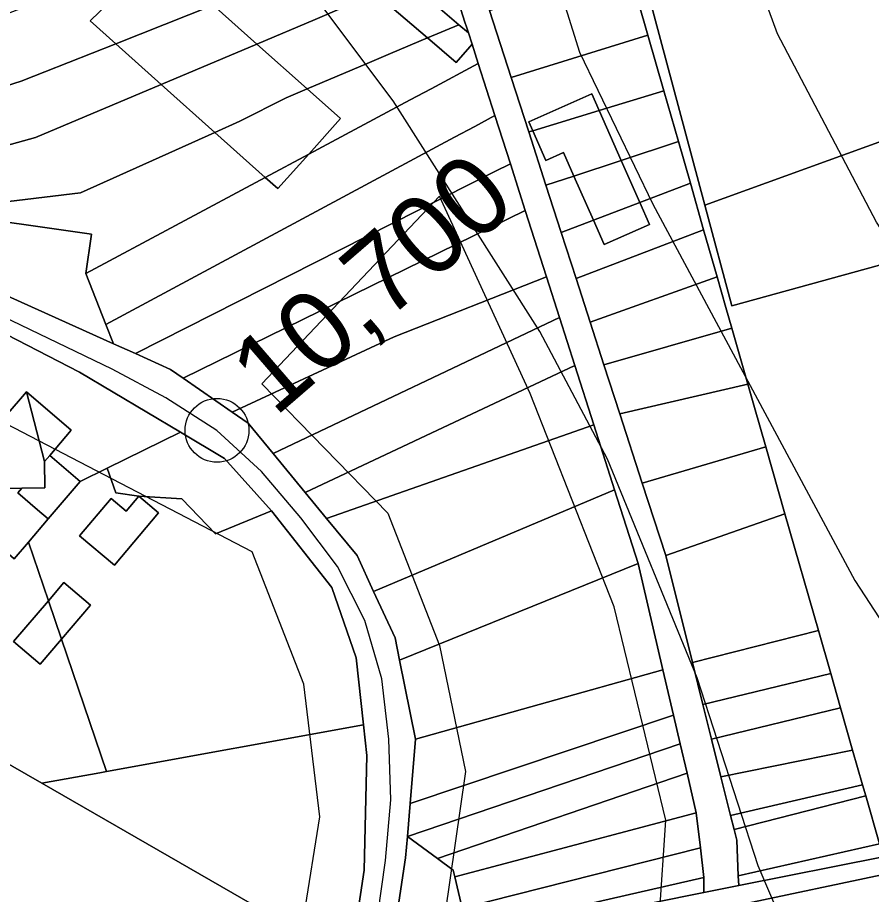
# Model space of a CAD drawing. Extents: x -510989 to -501240, y -1184665 to -1176089.
# Drawn here: x -509299.4 to -509158.8, y -1180046.7 to -1179902.3 of the extents above; entities that cross this region are included whole.
import ezdxf

# ---------------------------------------------------------------- set-up
doc = ezdxf.new("R2010")
doc.units = 0
for name, color, linetype in [('orna_puda', 7, 'Continuous'), ('ostatni_plocha_x_manipulacni_plocha', 7, 'Continuous'), ('STAV_systematicke_odvodneni', 7, 'Continuous'), ('trasovani_toku', 7, 'Continuous'), ('trvaly_travni_porost', 7, 'Continuous'), ('vodni_plocha_x_vodni_tok_v_koryte_umelem', 7, 'Continuous'), ('vrstevnice_01', 7, 'Continuous'), ('vrstevnice_02', 7, 'Continuous'), ('zastavena_plocha_a_nadvori', 7, 'Continuous')]:
    doc.layers.add(name, color=color, linetype=linetype)

msp = doc.modelspace()

# ---------------------------------------------------------------- linework, layer by layer
at = {"layer": 'orna_puda'}
msp.add_lwpolyline([(-509551.44, -1180058.44), (-509541.37, -1180032.19), (-509505.8, -1180014.94), (-509485.03, -1180004.33), (-509426.69, -1179970.89), (-509421.83, -1179967.93), (-509416.14, -1179964.47), (-509408.66, -1179958.69), (-509398.69, -1179948.99), (-509395.92, -1179946.29), (-509388.88, -1179961.65), (-509388.82, -1179965.62), (-509388.69, -1179974.07), (-509378.19, -1179980.22), (-509365.84, -1179987.46), (-509338.79, -1180003.3), (-509322.79, -1180012.68), (-509322.74, -1180012.71), (-509295.45, -1180028.39), (-509258.93, -1180049.38)], dxfattribs=at)
at = {"layer": 'ostatni_plocha_x_manipulacni_plocha'}
for points in [[(-509279.16, -1179893.19), (-509280.4, -1179894.4), (-509279.63, -1179895.2), (-509287.49, -1179902.86), (-509283.28, -1179906.61), (-509298.86, -1179912.78), (-509345.31, -1179927.56), (-509354.67, -1179922.9), (-509338.41, -1179915.88)], [(-509253.51, -1179894.83), (-509247.36, -1179892.39), (-509240.41, -1179898.36), (-509246.46, -1179900.92), (-509250.44, -1179902.6), (-509260.03, -1179906.66), (-509267.21, -1179900.25), (-509257.67, -1179896.48)], [(-509235.24, -1179896.18), (-509228.82, -1179893.47), (-509225.76, -1179903.05), (-509225.52, -1179903.8), (-509225.19, -1179904.81), (-509226.76, -1179903.47)], [(-509221.74, -1179901.11), (-509198.71, -1179894.43), (-509195.63, -1179905.19), (-509218.17, -1179912.14)], [(-509246.46, -1179900.92), (-509240.41, -1179898.36), (-509231.92, -1179905.65), (-509238.01, -1179908.23), (-509241.87, -1179909.86), (-509251.76, -1179914.04), (-509260.03, -1179906.66), (-509250.44, -1179902.6)], [(-509218.17, -1179912.14), (-509195.63, -1179905.19), (-509193, -1179914.38), (-509203.69, -1179917.62), (-509204.89, -1179914.88), (-509215.25, -1179919.45), (-509214.6, -1179920.92), (-509215.27, -1179921.12)], [(-509298.86, -1179912.78), (-509283.28, -1179906.61), (-509275.78, -1179913.31), (-509296.5, -1179922.05), (-509334.69, -1179932.64), (-509345.31, -1179927.56)], [(-509238.01, -1179908.23), (-509231.92, -1179905.65), (-509227.22, -1179909.7), (-509224.6, -1179906.65), (-509223.58, -1179909.86), (-509231.33, -1179914.01), (-509234.78, -1179915.86), (-509251.49, -1179924.79), (-509246.27, -1179918.94), (-509251.76, -1179914.04), (-509241.87, -1179909.86)], [(-509231.33, -1179914.01), (-509223.58, -1179909.86), (-509220.84, -1179918.43), (-509224.16, -1179920.21), (-509227.51, -1179922.01), (-509284.89, -1179952.84), (-509288.21, -1179944.42), (-509258.64, -1179928.61), (-509256.56, -1179930.46), (-509251.49, -1179924.79), (-509234.78, -1179915.86)], [(-509275.78, -1179913.31), (-509266.94, -1179921.2), (-509289.06, -1179931.17), (-509314.67, -1179934.24), (-509322.46, -1179933.61), (-509334.69, -1179932.64), (-509296.5, -1179922.05)], [(-509203.69, -1179917.62), (-509193, -1179914.38), (-509190.61, -1179922.72), (-509200.06, -1179925.84)], [(-509224.16, -1179920.21), (-509220.84, -1179918.43), (-509218.29, -1179926.38), (-509220.83, -1179927.67), (-509280, -1179957.64), (-509283.64, -1179956), (-509284.89, -1179952.84), (-509227.51, -1179922.01)], [(-509266.94, -1179921.2), (-509258.64, -1179928.61), (-509288.21, -1179944.42), (-509287.28, -1179937.97), (-509311.6, -1179934.48), (-509314.67, -1179934.24), (-509289.06, -1179931.17)], [(-509215.27, -1179921.12), (-509214.6, -1179920.92), (-509212.43, -1179925.82), (-509209.53, -1179924.54), (-509207.83, -1179928.4), (-509212.43, -1179929.91)], [(-509200.06, -1179925.84), (-509190.61, -1179922.72), (-509188.65, -1179929.58), (-509196.99, -1179932.77)], [(-509220.83, -1179927.67), (-509218.29, -1179926.38), (-509216.78, -1179931.09), (-509215.83, -1179934.07), (-509272.16, -1179961.67), (-509274.23, -1179960.24), (-509280, -1179957.64)], [(-509212.43, -1179929.91), (-509207.83, -1179928.4), (-509204.61, -1179935.68), (-509209.91, -1179937.7)], [(-509196.99, -1179932.77), (-509188.65, -1179929.58), (-509186.47, -1179937.23), (-509207.46, -1179945.27), (-509209.91, -1179937.7), (-509204.61, -1179935.68), (-509202.85, -1179939.66), (-509195.4, -1179936.37)], [(-509212.33, -1179945), (-509237.41, -1179954.86), (-509264.12, -1179967.25), (-509272.16, -1179961.67), (-509215.83, -1179934.07)], [(-509311.6, -1179934.48), (-509287.28, -1179937.97), (-509288.21, -1179944.42), (-509284.89, -1179952.84), (-509283.64, -1179956), (-509308.5, -1179944.81)], [(-509186.47, -1179937.23), (-509184.24, -1179945.01), (-509205.14, -1179952.44), (-509207.46, -1179945.27)], [(-509210.2, -1179951.69), (-509257.36, -1179974.08), (-509261.47, -1179969.08), (-509264.12, -1179967.25), (-509237.41, -1179954.86), (-509212.33, -1179945)], [(-509184.24, -1179945.01), (-509182.8, -1179950.04), (-509181.82, -1179953.46), (-509202.87, -1179959.47), (-509205.14, -1179952.44)], [(-509308.37, -1179951.14), (-509303.03, -1179953.6), (-509289.24, -1179960.67), (-509272.59, -1179970.58), (-509284.66, -1179976.49), (-509289.12, -1179978.67), (-509294.14, -1179974.39), (-509290.6, -1179970.25), (-509297.99, -1179963.94), (-509301.31, -1179967.84), (-509303.11, -1179962.06)], [(-509207.66, -1179959.6), (-509252.09, -1179980.48), (-509257.36, -1179974.08), (-509210.2, -1179951.69)], [(-509202.87, -1179959.47), (-509181.82, -1179953.46), (-509179.19, -1179962.66), (-509200.25, -1179967.55)], [(-509204.54, -1179969.37), (-509248.57, -1179984.76), (-509252.09, -1179980.48), (-509207.66, -1179959.6)], [(-509179.19, -1179962.66), (-509178.09, -1179966.51), (-509176.23, -1179972.99), (-509196.56, -1179978.97), (-509200.25, -1179967.55)], [(-509201.12, -1179980.06), (-509240.8, -1179996.81), (-509243.51, -1179990.9), (-509248.57, -1179984.76), (-509204.54, -1179969.37)], [(-509272.59, -1179970.58), (-509265.34, -1179974.89), (-509257.62, -1179983.54), (-509266.85, -1179987.32), (-509272.39, -1179981.57), (-509279.49, -1179981.11), (-509283.26, -1179980.55), (-509284.66, -1179976.49)], [(-509196.56, -1179978.97), (-509176.23, -1179972.99), (-509173.08, -1179984), (-509192.71, -1179990.88)], [(-509283.26, -1179980.55), (-509279.49, -1179981.11), (-509281.57, -1179983.59), (-509284.05, -1179981.5), (-509289.22, -1179987.65), (-509283.48, -1179992.48), (-509276.22, -1179983.86), (-509279.49, -1179981.11), (-509272.39, -1179981.57), (-509266.85, -1179987.32), (-509257.62, -1179983.54), (-509247.71, -1179996.14), (-509243.68, -1180007.74), (-509242.47, -1180018.79), (-509284.8, -1180026.46), (-509292.2, -1180004.67), (-509287.42, -1179999.06), (-509291.8, -1179995.32), (-509294.36, -1179998.32), (-509297.64, -1179988.66), (-509294.4, -1179984.86), (-509289.12, -1179978.67), (-509284.66, -1179976.49)], [(-509310.38, -1179979.84), (-509306.18, -1179979.82), (-509309.3, -1179983.48), (-509301.77, -1179989.91), (-509300, -1179991.42), (-509297.64, -1179988.66), (-509294.36, -1179998.32), (-509300.1, -1180005.03), (-509295.72, -1180008.78), (-509292.2, -1180004.67), (-509284.8, -1180026.46), (-509285.9, -1180026.66), (-509295.45, -1180028.39), (-509322.74, -1180012.71), (-509322.79, -1180012.68), (-509323.67, -1179999.16), (-509324.04, -1179993.42), (-509324.91, -1179979.92)], [(-509197.23, -1179992.2), (-509236.54, -1180008.14), (-509237.28, -1180004.46), (-509240.8, -1179996.81), (-509201.12, -1179980.06)], [(-509192.71, -1179990.88), (-509173.08, -1179984), (-509167.57, -1180003.21), (-509188.32, -1180008.48)], [(-509197.23, -1179992.2), (-509193.16, -1180009.68), (-509233.9, -1180021.14), (-509236.54, -1180008.14)], [(-509291.8, -1179995.32), (-509287.42, -1179999.06), (-509292.2, -1180004.67), (-509294.36, -1179998.32)], [(-509294.36, -1179998.32), (-509292.2, -1180004.67), (-509295.72, -1180008.78), (-509300.1, -1180005.03)], [(-509188.32, -1180008.48), (-509167.57, -1180003.21), (-509165.54, -1180010.3), (-509186.6, -1180015.39)], [(-509191.41, -1180017.18), (-509234.79, -1180031.74), (-509233.9, -1180021.14), (-509193.16, -1180009.68)], [(-509186.6, -1180015.39), (-509165.54, -1180010.3), (-509163.91, -1180015.98), (-509185.17, -1180021.13)], [(-509185.17, -1180021.13), (-509163.91, -1180015.98), (-509161.92, -1180022.94), (-509183.62, -1180027.33)], [(-509190.31, -1180021.9), (-509235.25, -1180037.15), (-509234.79, -1180031.74), (-509191.41, -1180017.18)], [(-509242.47, -1180018.79), (-509241.92, -1180023.82), (-509242.38, -1180042.72), (-509244.6, -1180057.62), (-509258.93, -1180049.38), (-509295.45, -1180028.39), (-509285.9, -1180026.66), (-509284.8, -1180026.46)], [(-509189.19, -1180026.73), (-509230.29, -1180040.79), (-509235.25, -1180037.15), (-509190.31, -1180021.9)], [(-509183.62, -1180027.33), (-509161.92, -1180022.94), (-509160.28, -1180028.67), (-509182.03, -1180033.71)], [(-509187.67, -1180033.24), (-509227.45, -1180043.8), (-509227.72, -1180042.68), (-509230.29, -1180040.79), (-509189.19, -1180026.73)], [(-509160.28, -1180028.67), (-509159.77, -1180030.43), (-509181.46, -1180036), (-509182.03, -1180033.71)], [(-509159.77, -1180030.43), (-509157.5, -1180038.36), (-509180.75, -1180043.64), (-509181.02, -1180037.75), (-509181.46, -1180036)], [(-509187, -1180039.03), (-509226.2, -1180048.93), (-509227.45, -1180043.8), (-509187.67, -1180033.24)], [(-509235.55, -1180040.66), (-509235.25, -1180037.15), (-509230.29, -1180040.79), (-509227.72, -1180042.68), (-509227.45, -1180043.8), (-509226.2, -1180048.93), (-509225.27, -1180052.78), (-509237.8, -1180055.64)], [(-509186.43, -1180043.93), (-509225.27, -1180052.78), (-509226.2, -1180048.93), (-509187, -1180039.03)], [(-509157.5, -1180038.36), (-509156.89, -1180040.5), (-509180.67, -1180045.24), (-509180.75, -1180043.64)], [(-509186.43, -1180043.93), (-509186.43, -1180046.39), (-509212.09, -1180051.51), (-509224.93, -1180054.2), (-509225.27, -1180052.78)]]:
    msp.add_lwpolyline(points, close=True, dxfattribs=at)
msp.add_lwpolyline([(-509221.74, -1179901.11), (-509218.17, -1179912.14), (-509215.27, -1179921.12), (-509212.43, -1179929.91), (-509209.91, -1179937.7), (-509207.46, -1179945.27), (-509205.14, -1179952.44), (-509202.87, -1179959.47), (-509200.25, -1179967.55), (-509196.56, -1179978.97), (-509192.71, -1179990.88), (-509188.32, -1180008.48), (-509186.6, -1180015.39), (-509185.17, -1180021.13), (-509183.62, -1180027.33), (-509182.03, -1180033.71), (-509181.46, -1180036), (-509181.02, -1180037.75), (-509180.75, -1180043.64), (-509180.67, -1180045.24), (-509186.43, -1180046.39), (-509186.43, -1180043.93), (-509187, -1180039.03), (-509187.67, -1180033.24), (-509189.19, -1180026.73), (-509190.31, -1180021.9), (-509191.41, -1180017.18), (-509193.16, -1180009.68), (-509197.23, -1179992.2), (-509201.12, -1179980.06), (-509204.54, -1179969.37), (-509207.66, -1179959.6), (-509210.2, -1179951.69), (-509212.33, -1179945), (-509215.83, -1179934.07), (-509216.78, -1179931.09), (-509218.29, -1179926.38), (-509220.84, -1179918.43), (-509223.58, -1179909.86), (-509224.6, -1179906.65), (-509225.19, -1179904.81), (-509225.52, -1179903.8), (-509225.76, -1179903.05), (-509228.82, -1179893.47)], dxfattribs=at)
at = {"layer": 'STAV_systematicke_odvodneni'}
for p, q in [((-509260.83, -1179990.26), (-509401.27, -1179917.35)), ((-509229.95, -1179931.73), (-509259.2, -1179962.6)), ((-509215.05, -1179964.19), (-509229.95, -1179931.73)), ((-509259.2, -1179962.6), (-509238.46, -1179983.89)), ((-509201.22, -1179999.32), (-509215.05, -1179964.19)), ((-509238.46, -1179983.89), (-509229.95, -1180005.71)), ((-509252.32, -1180012.08), (-509260.83, -1179990.26)), ((-509192.71, -1180034.44), (-509201.22, -1179999.32)), ((-509229.95, -1180005.71), (-509225.69, -1180026.46)), ((-509249.66, -1180033.9), (-509252.32, -1180012.08)), ((-509225.69, -1180026.46), (-509236.86, -1180104.7)), ((-509257.1, -1180080.2), (-509249.66, -1180033.9)), ((-509194.3, -1180058.93), (-509192.71, -1180034.44))]:
    msp.add_line(p, q, dxfattribs=at)
at = {"layer": 'trasovani_toku'}
for p, q in [((-509292.86, -1179955.85), (-509301.87, -1179951.51)), ((-509283.84, -1179960.17), (-509292.86, -1179955.85)), ((-509275.04, -1179964.9), (-509283.84, -1179960.17)), ((-509266.6, -1179970.27), (-509275.04, -1179964.9)), ((-509259.27, -1179977.07), (-509266.6, -1179970.27)), ((-509252.79, -1179984.69), (-509259.27, -1179977.07)), ((-509246.77, -1179992.68), (-509252.79, -1179984.69)), ((-509242.25, -1180001.59), (-509246.77, -1179992.68)), ((-509239.47, -1180011.2), (-509242.25, -1180001.59)), ((-509238.28, -1180021.13), (-509239.47, -1180011.2)), ((-509237.95, -1180031.12), (-509238.28, -1180021.13)), ((-509238.87, -1180041.08), (-509237.95, -1180031.12)), ((-509240.27, -1180050.98), (-509238.87, -1180041.08))]:
    msp.add_line(p, q, dxfattribs=at)
msp.add_circle((-509266.6, -1179970.27), 5.25, dxfattribs=at)
at = {"layer": 'trvaly_travni_porost'}
for points in [[(-508840.82, -1179809.47), (-508838.23, -1179816.59), (-508839.97, -1179824.86), (-508838.61, -1179839.98), (-508839.06, -1179845.97), (-508839.44, -1179851.07), (-508860.61, -1179856.49), (-508972.97, -1179893.55), (-508975.76, -1179885.1), (-509068.15, -1179907.03), (-509094.26, -1179909.58), (-509125.58, -1179916.86), (-509152.59, -1179920.98), (-509186.27, -1179933.21), (-509197.76, -1179890.25), (-509162.53, -1179880.9), (-509006.35, -1179847.7), (-508948.92, -1179833.69), (-508843.75, -1179801.39)], [(-508839.44, -1179851.07), (-508840.15, -1179860.69), (-508967.27, -1179901.72), (-509006.01, -1179912.33), (-509076.57, -1179927.87), (-509150.51, -1179941.15), (-509181.84, -1179949.78), (-509186.27, -1179933.21), (-509152.59, -1179920.98), (-509125.58, -1179916.86), (-509094.26, -1179909.58), (-509068.15, -1179907.03), (-508975.76, -1179885.1), (-508972.97, -1179893.55), (-508860.61, -1179856.49)], [(-509156.1, -1180043.26), (-509180.52, -1180048.42), (-509186.43, -1180049.67), (-509238.55, -1180060.68), (-509237.99, -1180056.93), (-509224.93, -1180054.2), (-509212.09, -1180051.51), (-509186.43, -1180046.39), (-509180.67, -1180045.24), (-509156.89, -1180040.5)]]:
    msp.add_lwpolyline(points, close=True, dxfattribs=at)
for points in [[(-509197.76, -1179890.25), (-509186.27, -1179933.21), (-509181.84, -1179949.78), (-509150.51, -1179941.15)], [(-509157.5, -1180038.36), (-509159.77, -1180030.43), (-509160.28, -1180028.67), (-509161.92, -1180022.94), (-509163.91, -1180015.98), (-509165.54, -1180010.3), (-509167.57, -1180003.21), (-509173.08, -1179984), (-509176.23, -1179972.99), (-509178.09, -1179966.51), (-509179.19, -1179962.66), (-509181.82, -1179953.46), (-509182.8, -1179950.04), (-509184.24, -1179945.01), (-509186.47, -1179937.23), (-509188.65, -1179929.58), (-509190.61, -1179922.72), (-509193, -1179914.38), (-509195.63, -1179905.19), (-509198.71, -1179894.43)], [(-509180.52, -1180048.42), (-509156.1, -1180043.26)]]:
    msp.add_lwpolyline(points, dxfattribs=at)
at = {"layer": 'vodni_plocha_x_vodni_tok_v_koryte_umelem'}
for points in [[(-509244.6, -1180057.62), (-509242.38, -1180042.72), (-509241.92, -1180023.82), (-509242.47, -1180018.79), (-509243.68, -1180007.74), (-509247.71, -1179996.14), (-509257.62, -1179983.54), (-509265.34, -1179974.89), (-509272.59, -1179970.58), (-509289.24, -1179960.67), (-509303.03, -1179953.6), (-509308.37, -1179951.14), (-509321.23, -1179945.22), (-509334.45, -1179939.13), (-509345.54, -1179934.02), (-509354.68, -1179929.82), (-509363.35, -1179925.82), (-509373.34, -1179921.23), (-509373.43, -1179921.18), (-509376.83, -1179919.53), (-509378.36, -1179918.79), (-509387.29, -1179914.47), (-509389.38, -1179913.45)], [(-509308.5, -1179944.81), (-509283.64, -1179956), (-509280, -1179957.64), (-509274.23, -1179960.24), (-509272.16, -1179961.67), (-509264.12, -1179967.25), (-509261.47, -1179969.08), (-509257.36, -1179974.08), (-509252.09, -1179980.48), (-509248.57, -1179984.76), (-509243.51, -1179990.9), (-509240.8, -1179996.81), (-509237.28, -1180004.46), (-509236.54, -1180008.14), (-509233.9, -1180021.14), (-509234.79, -1180031.74), (-509235.25, -1180037.15), (-509235.55, -1180040.66), (-509237.8, -1180055.64)]]:
    msp.add_lwpolyline(points, dxfattribs=at)
at = {"layer": 'vrstevnice_01'}
for points in [[(-509072.09, -1180061), (-509089.69, -1180042), (-509102.5, -1180024), (-509126.59, -1179984), (-509158, -1179936), (-509174.31, -1179905), (-509181.59, -1179885), (-509184.31, -1179864), (-509184, -1179849), (-509182.31, -1179842), (-509180.59, -1179821), (-509181.81, -1179807), (-509187, -1179794), (-509194.81, -1179785), (-509205.91, -1179777), (-509230.41, -1179766), (-509254.69, -1179747), (-509275.5, -1179741), (-509305.69, -1179737), (-509320.19, -1179734), (-509338.31, -1179724), (-509350.81, -1179712), (-509367.09, -1179690), (-509378.31, -1179665)], [(-509160.41, -1180082), (-509177.5, -1180042), (-509187.5, -1180011), (-509202.31, -1179975), (-509213.41, -1179954), (-509237.59, -1179916), (-509250.31, -1179899), (-509263.41, -1179885), (-509282.5, -1179870), (-509327.59, -1179841), (-509352.19, -1179821), (-509378.5, -1179796), (-509418.81, -1179754)]]:
    msp.add_lwpolyline(points, dxfattribs=at)
at = {"layer": 'vrstevnice_02'}
msp.add_lwpolyline([(-509393.19, -1179727), (-509369, -1179750), (-509360, -1179756), (-509336.5, -1179767), (-509286.09, -1179784), (-509270.41, -1179790), (-509248.69, -1179806), (-509243.81, -1179811), (-509236.69, -1179822), (-509226, -1179847), (-509206.91, -1179908), (-509194.81, -1179933), (-509161.59, -1179995), (-509140.69, -1180027), (-509125.5, -1180062)], dxfattribs=at)
at = {"layer": 'zastavena_plocha_a_nadvori'}
for points in [[(-509273.44, -1179890.5), (-509273.41, -1179890.99), (-509273.33, -1179892.18), (-509274.62, -1179893.63), (-509267.21, -1179900.25), (-509283.28, -1179906.61), (-509287.49, -1179902.86), (-509279.63, -1179895.2), (-509280.4, -1179894.4), (-509279.16, -1179893.19), (-509276.22, -1179890.32)], [(-509240.41, -1179898.36), (-509235.24, -1179896.18), (-509226.76, -1179903.47), (-509231.92, -1179905.65)], [(-509283.28, -1179906.61), (-509267.21, -1179900.25), (-509260.03, -1179906.66), (-509275.78, -1179913.31)], [(-509225.19, -1179904.81), (-509224.6, -1179906.65), (-509227.22, -1179909.7), (-509231.92, -1179905.65), (-509226.76, -1179903.47)], [(-509275.78, -1179913.31), (-509260.03, -1179906.66), (-509251.76, -1179914.04), (-509255.21, -1179915.5), (-509262.82, -1179919.35), (-509266.94, -1179921.2)], [(-509255.21, -1179915.5), (-509251.76, -1179914.04), (-509246.27, -1179918.94), (-509251.49, -1179924.79), (-509258.64, -1179928.61), (-509266.94, -1179921.2), (-509262.82, -1179919.35)], [(-509204.89, -1179914.88), (-509203.69, -1179917.62), (-509214.6, -1179920.92), (-509215.25, -1179919.45)], [(-509214.6, -1179920.92), (-509203.69, -1179917.62), (-509200.06, -1179925.84), (-509207.83, -1179928.4), (-509209.53, -1179924.54), (-509212.43, -1179925.82)], [(-509258.64, -1179928.61), (-509251.49, -1179924.79), (-509256.56, -1179930.46)], [(-509207.83, -1179928.4), (-509200.06, -1179925.84), (-509196.99, -1179932.77), (-509204.61, -1179935.68)], [(-509204.61, -1179935.68), (-509196.99, -1179932.77), (-509195.4, -1179936.37), (-509202.85, -1179939.66)], [(-509315.11, -1179950.44), (-509306.43, -1179957.84), (-509307.12, -1179958.64), (-509303.11, -1179962.06), (-509305.2, -1179964.51), (-509301.31, -1179967.84), (-509297.99, -1179963.94), (-509294.99, -1179975.38), (-509294.96, -1179979.76), (-509298.74, -1179979.78), (-509306.18, -1179979.82), (-509311.8, -1179975.02), (-509318.04, -1179953.87)], [(-509290.6, -1179970.25), (-509294.14, -1179974.39), (-509294.99, -1179975.38), (-509297.99, -1179963.94)], [(-509294.99, -1179975.38), (-509294.14, -1179974.39), (-509289.12, -1179978.67), (-509294.4, -1179984.86), (-509296.17, -1179983.35), (-509299.42, -1179980.58), (-509298.74, -1179979.78), (-509294.96, -1179979.76)], [(-509306.18, -1179979.82), (-509298.74, -1179979.78), (-509299.42, -1179980.58), (-509296.17, -1179983.35), (-509294.4, -1179984.86), (-509297.64, -1179988.66), (-509300, -1179991.42), (-509301.77, -1179989.91), (-509309.3, -1179983.48)], [(-509279.49, -1179981.11), (-509276.22, -1179983.86), (-509283.48, -1179992.48), (-509289.22, -1179987.65), (-509284.05, -1179981.5), (-509281.57, -1179983.59)]]:
    msp.add_lwpolyline(points, close=True, dxfattribs=at)

# ---------------------------------------------------------------- texts
at = {"layer": 'trasovani_toku'}
msp.add_text('10,700', height=13, rotation=40.8066, dxfattribs=at).set_placement((-509257.09, -1179968.22))

doc.saveas('drawing.dxf')
